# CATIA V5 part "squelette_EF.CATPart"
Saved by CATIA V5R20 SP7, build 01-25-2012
Part number: squelette_EF
Publications: "F'", "FF'", "barre_EF", "axe.pivot.F", "axe.pivot.E", "Plan.pivot.F", "Plan.pivot.E"
Bounding box of the stored display mesh (mm): x -4.1 to 22.1, y -46.096 to 18.5, z -8.5 to 3.546
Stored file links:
  F:\IAO\Catia\squelette_EF.CATPart
  F:\IAO\Catia\squelette.CATProduct
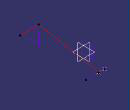
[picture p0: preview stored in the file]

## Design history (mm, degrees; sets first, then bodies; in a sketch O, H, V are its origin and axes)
Set1
  Plane1 "Plan.2,1": linked copy from another document
  Point1 "F": linked copy from another document
  Point2 "E": linked copy from another document
  Plane2 "plan.bati": linked copy from another document
Set2
  Point3 "F'": type OnPlane, Support Plane1, H 18.5, V -8.5, Direction (0, 1, 0)
  Line1 "FF'": type PtPt, FirstPoint Point3, SecondPoint Point1
  Line2 "barre_EF": type PtPt, FirstPoint Point3, SecondPoint Point2, Support Plane1
  Line3 "axe.pivot.E": type Normal, RefPoint Point2, RefSkin Plane1, Start 0, End 20
  Line4 "axe.pivot.F": type Normal, RefPoint Point1, RefSkin Plane1, Start 0, End 20
  Plane3 "Plan.pivot.E": type Offset, RefPlane Plane1, Offset 0
  Plane4 "Plan.pivot.F": type Offset, RefPlane Plane2, Offset 0
Body1 (main body)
